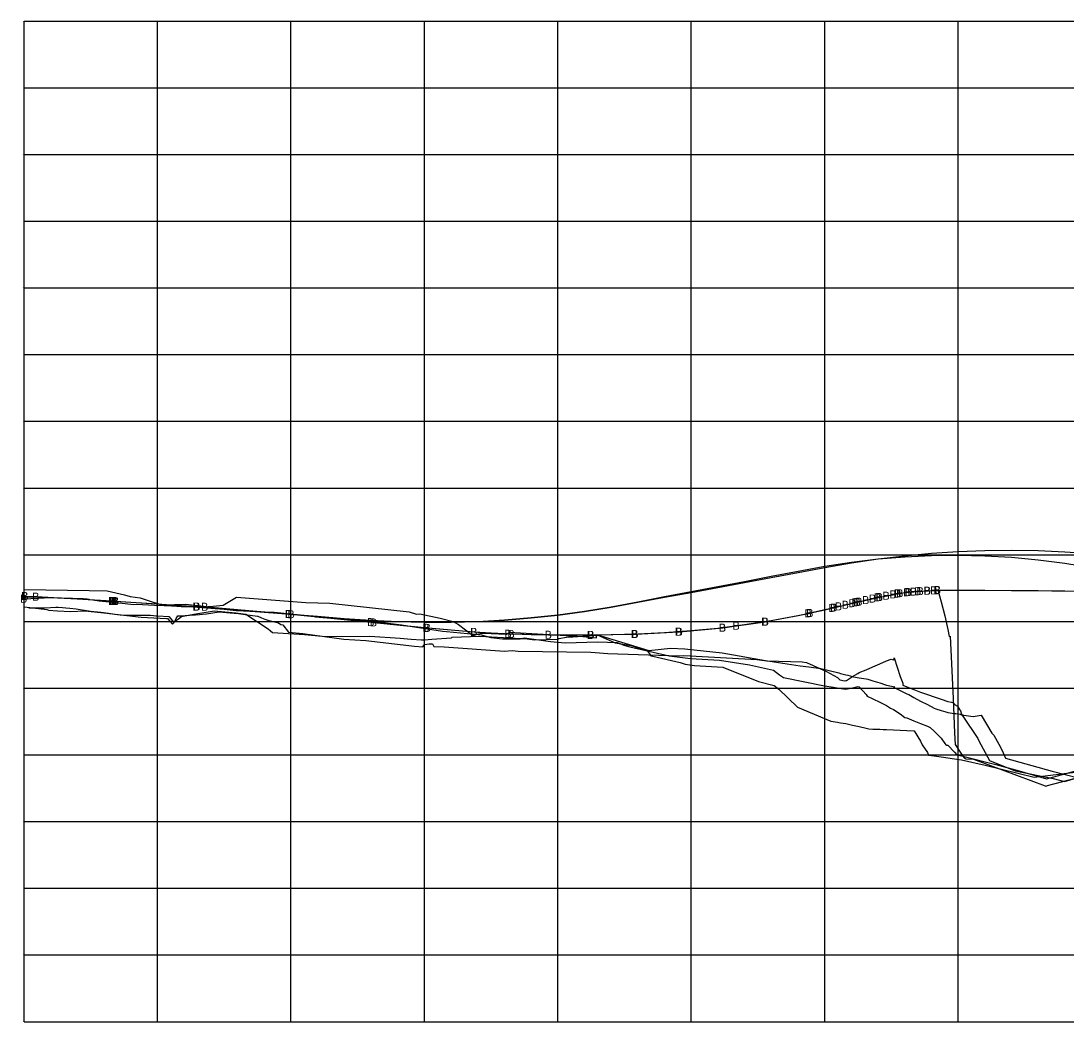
# Model space of a CAD drawing. Extents: x 76292 to 78417, y 50412 to 52585.
# Drawn here: x 76304.2 to 76695.8, y 50411.8 to 50787.4 of the extents above; entities that cross this region are included whole.
import ezdxf

# ---------------------------------------------------------------- set-up
doc = ezdxf.new("R2010")
doc.units = 0
for name, color, linetype in [('1', 7, 'Continuous'), ('2', 7, 'Continuous'), ('38', 7, 'Continuous'), ('5', 7, 'Continuous'), ('63', 7, 'Continuous')]:
    doc.layers.add(name, color=color, linetype=linetype)

msp = doc.modelspace()

# ---------------------------------------------------------------- linework, layer by layer
at = {"layer": '1'}
for p, q in [((76305.34, 50412.34), (78205.34, 50412.34)), ((76305.34, 50412.34), (76305.34, 50412.34)), ((76355.34, 50412.34), (76355.34, 50412.34)), ((76405.34, 50412.34), (76405.34, 50412.34)), ((76455.34, 50412.34), (76455.34, 50412.34)), ((76505.34, 50412.34), (76505.34, 50412.34)), ((76555.34, 50412.34), (76555.34, 50412.34)), ((76605.34, 50412.34), (76605.34, 50412.34)), ((76655.34, 50412.34), (76655.34, 50412.34))]:
    msp.add_line(p, q, dxfattribs=at)
for points in [[(76305.34, 50574.3), (76329.72, 50573.94), (76336.54, 50573.87), (76342.97, 50572.34), (76345.12, 50571.75), (76348.82, 50571.14), (76351.86, 50570.18), (76356.85, 50568.54), (76357.53, 50568.62), (76365.83, 50568.81), (76372.74, 50568.03), (76373.97, 50567.86), (76374.28, 50567.9), (76376.18, 50568.07), (76379.92, 50568.38), (76384.91, 50571.48), (76410.89, 50569.47), (76419.91, 50569.23), (76449.64, 50566), (76452.37, 50565.05), (76453.69, 50565.21), (76461.28, 50563.57), (76466.12, 50562.33), (76468.11, 50561.15), (76473.42, 50557.15), (76476.75, 50557.92), (76476.95, 50557.94), (76477.55, 50558), (76486.06, 50557.61), (76487.36, 50558.27), (76489.3, 50558.23), (76514.73, 50556.72), (76519.84, 50556.23), (76519.89, 50556.66), (76520.07, 50557.36), (76526.79, 50554.3), (76532.67, 50553.29), (76538.88, 50551.39), (76540.2, 50549.47), (76540.92, 50549.32), (76551.13, 50546.98), (76553.01, 50546.28), (76556.53, 50545.81), (76567.14, 50545.26), (76580.58, 50539.89), (76586.39, 50538.33), (76588.21, 50537.01), (76595.11, 50530.17), (76607.69, 50524.96), (76610.19, 50524.54), (76610.66, 50524.47), (76611.28, 50524.37), (76613.21, 50524.04), (76615.76, 50523.5), (76618.31, 50522.95), (76620.86, 50522.39), (76621.87, 50522.04), (76623.41, 50522.01), (76625.97, 50521.92), (76627.2, 50521.87), (76628.52, 50521.83), (76631.07, 50521.71), (76633.62, 50521.59), (76636.17, 50521.47), (76638.72, 50521.35), (76638.9, 50521.34), (76641.27, 50517.5), (76641.82, 50516.11), (76643.82, 50513.23), (76644.22, 50512.24), (76646.37, 50511.96), (76648.93, 50511.58), (76651.48, 50511.2), (76654.03, 50510.83), (76656.58, 50510.44), (76665.41, 50508.46), (76683.8, 50504.01), (76700.19, 50506.03)], [(76305.34, 50571.97), (76306.2, 50571.59), (76306.58, 50571.58), (76306.91, 50571.57), (76307.23, 50571.55), (76327.44, 50570.88), (76327.97, 50570.85), (76328.21, 50570.83), (76328.44, 50570.82), (76328.67, 50570.79), (76328.89, 50570.77), (76329.11, 50570.74), (76329.33, 50570.71), (76329.57, 50570.67), (76329.82, 50570.62), (76329.86, 50570.61), (76329.9, 50570.6), (76331.09, 50570.39), (76333.55, 50570.08), (76342.1, 50569.17), (76345.39, 50568.83), (76349.71, 50568.63), (76354.25, 50568.43), (76357.89, 50568.26), (76360.59, 50568.14), (76362.63, 50568.05), (76364.16, 50567.98), (76365.32, 50567.93), (76366.19, 50567.9), (76366.83, 50567.88), (76369.95, 50567.94), (76372.79, 50567.62), (76373.42, 50567.56), (76374.35, 50567.48), (76375.76, 50567.35), (76377.58, 50567.18), (76380.33, 50566.91), (76384.81, 50566.44), (76385.18, 50566.4), (76397.24, 50565.85), (76398.15, 50565.81), (76398.35, 50565.8), (76398.49, 50565.79), (76398.6, 50565.79), (76398.69, 50565.79), (76398.76, 50565.79), (76398.83, 50565.8), (76398.84, 50565.8), (76398.85, 50565.8), (76398.94, 50565.81), (76399.03, 50565.81), (76399.12, 50565.81), (76413.77, 50564.33), (76413.95, 50564.32), (76414.52, 50564.08), (76417.31, 50563.84), (76436.78, 50562.3), (76446.75, 50561.06), (76462.16, 50558.66), (76463.6, 50558.58), (76476.69, 50557.29), (76477.49, 50557.11), (76480.24, 50556.32), (76484.67, 50555.83), (76491.27, 50555.84), (76491.46, 50555.96), (76492.91, 50556.24), (76502.55, 50554.77), (76508.12, 50554.35), (76520.31, 50554.65), (76527.55, 50554.45), (76530.41, 50553.32), (76532.31, 50552.86), (76547.08, 50549.49), (76555.06, 50548.5), (76565.96, 50547.79), (76577.22, 50546.13), (76586.18, 50544.08), (76588.45, 50542.38), (76589.96, 50541.39), (76605.32, 50538.21), (76608.58, 50537.66), (76610.66, 50537.33), (76613.21, 50536.97), (76613.3, 50536.96), (76615.76, 50537.52), (76617.74, 50538), (76618.31, 50537.81), (76620.86, 50534.94), (76621.28, 50534.37), (76623.41, 50533.34), (76625.97, 50532.06), (76628.52, 50530.78), (76629.98, 50529.89), (76631.07, 50529.37), (76633.62, 50527.71), (76635.34, 50526.36), (76636.17, 50526.17), (76638.72, 50525.15), (76641.27, 50524.12), (76643.82, 50523.1), (76644.87, 50522.59), (76646.37, 50521.23), (76648.93, 50518.54), (76650.41, 50516.66), (76650.76, 50516.16), (76651.01, 50515.99), (76651.48, 50515.94), (76654.03, 50513.32), (76654.83, 50512.33), (76656.58, 50512), (76669.47, 50508.75), (76678.2, 50506.3), (76688.47, 50503.33), (76708.61, 50508.87)], [(76305.34, 50567.76), (76313.87, 50566.77), (76314.52, 50566.55), (76317.91, 50566.33), (76322.78, 50566.06), (76328.07, 50566.36), (76335.22, 50565.54), (76349.2, 50563.89), (76358.7, 50563.47), (76359.13, 50563.5), (76360.89, 50561.5), (76360.99, 50561.38), (76361.36, 50561.7), (76361.46, 50561.84), (76361.67, 50562.17), (76362.38, 50563.43), (76362.92, 50564.47), (76363.96, 50564.5), (76367.33, 50564.65), (76369.54, 50564.78), (76371.08, 50564.9), (76372.19, 50565.01), (76373.67, 50565.19), (76378.48, 50565.98), (76382.54, 50565.62), (76384.09, 50565.48), (76385.7, 50565.26), (76388.2, 50564.9), (76390.12, 50564.65), (76392.87, 50564.32), (76392.93, 50564.32), (76394.34, 50563.67), (76395.58, 50563.2), (76396.65, 50562.87), (76400.73, 50561.83), (76401.5, 50561.21), (76402.3, 50561.06), (76404.41, 50558.34), (76409.81, 50557.81), (76425.22, 50555.73), (76433.44, 50555.15), (76451.63, 50553.1), (76454.73, 50552.85), (76455.45, 50553.68), (76457.13, 50553.94), (76458.42, 50553.91), (76458.83, 50553.01), (76462.8, 50552.84), (76485.41, 50551.21), (76488.23, 50551.43), (76490.43, 50551.19), (76517.68, 50550.77), (76519.35, 50550.76), (76524.11, 50550.34), (76550.67, 50549.51), (76552.44, 50549.55), (76554.98, 50549.41), (76579.96, 50548.07), (76583.63, 50547.6), (76596.94, 50547.19), (76598.5, 50546.95), (76606.05, 50543.63), (76610.17, 50541.3), (76610.66, 50540.82), (76610.99, 50540.49), (76612.7, 50540.13), (76613.21, 50540.19), (76613.53, 50540.21), (76615.76, 50541.69), (76617.81, 50542.83), (76618.31, 50543.15), (76620.86, 50544.22), (76623.41, 50545.31), (76625.97, 50546.41), (76628.52, 50547.54), (76630.2, 50548.18), (76631.07, 50547.92), (76631.29, 50547.88), (76631.4, 50548.71), (76633.62, 50541.73), (76634.62, 50539.16), (76634.67, 50538.51), (76636.17, 50537.83), (76638.72, 50536.81), (76641.27, 50535.84), (76643.82, 50534.92), (76646.37, 50534.03), (76648.93, 50533.19), (76651.48, 50532.39), (76652.91, 50532.03), (76653.46, 50531.81), (76654.03, 50531.22), (76655.04, 50530.64), (76655.49, 50529.96), (76655.81, 50529.4), (76656.17, 50528.8), (76656.58, 50527.54), (76657.06, 50526.81), (76662.78, 50518.42), (76663.07, 50517.59), (76667.07, 50510.23), (76676.66, 50506.39), (76691, 50503.47), (76695.17, 50502.34), (76717.36, 50508.88)], [(76307.14, 50567.5), (76313.25, 50567.45), (76317.22, 50567.75), (76318.12, 50567.7), (76319.8, 50567.57), (76320.95, 50567.48), (76322.54, 50567.29), (76324.92, 50567.01), (76330.3, 50566.25), (76334.07, 50565.77), (76337, 50565.39), (76339.36, 50565.1), (76341.32, 50564.87), (76343, 50564.67), (76352.75, 50564.64), (76353.83, 50564.55), (76354.75, 50564.47), (76355.53, 50564.41), (76359.55, 50564.22), (76360.91, 50562.58), (76361.32, 50562.11), (76363.28, 50563.35), (76364.4, 50564.24), (76367.57, 50564.78), (76369.01, 50565.06), (76376.54, 50566.3), (76384.69, 50565.58), (76388.41, 50565.07), (76388.43, 50565.07), (76388.45, 50565.06), (76396.82, 50559.51), (76397.68, 50558.84), (76398.5, 50558.14), (76410.39, 50557.46), (76418.27, 50556.64), (76434.85, 50556.79), (76446.23, 50556.13), (76450.39, 50555.76), (76454.32, 50555.4), (76455.33, 50555.43), (76458.19, 50555.75), (76465.5, 50556.26), (76465.73, 50556.39), (76476.11, 50556.77), (76493.81, 50555.81), (76493.9, 50555.79), (76496.63, 50555.5), (76505.35, 50555.72), (76505.68, 50555.89), (76508.55, 50556.41), (76509.32, 50556.54), (76510.92, 50556.56), (76518.32, 50557.06), (76520.23, 50557.14), (76520.86, 50557.08), (76521.42, 50556.89), (76539.45, 50551.47), (76547.61, 50552.37), (76552.97, 50552.11), (76566.9, 50550.6), (76583.21, 50547.69), (76596.17, 50545.76), (76599.39, 50545.28), (76603.86, 50544.74), (76610.66, 50543.03), (76611.32, 50542.86), (76613.21, 50542.38), (76613.99, 50542.24), (76615.76, 50541.71), (76616.17, 50541.63), (76618.31, 50541.24), (76620.86, 50540.81), (76621.45, 50540.74), (76623.41, 50540.07), (76625.97, 50539.28), (76628.52, 50538.5), (76631.63, 50537.81), (76631.07, 50537.7), (76633.62, 50536.43), (76636.17, 50535.17), (76636.89, 50534.91), (76638.72, 50533.85), (76641.27, 50532.52), (76643.82, 50531.2), (76646.37, 50529.9), (76647.04, 50529.65), (76648.93, 50528.95), (76650.75, 50528.48), (76651.48, 50528.27), (76654.03, 50527.84), (76654.43, 50527.78), (76656.17, 50527.6), (76656.58, 50527.4), (76660.96, 50526.69), (76664, 50527.25), (76668.02, 50520.51), (76668.66, 50519.7), (76670.53, 50516.34), (76671.86, 50513.98), (76673.1, 50511.07), (76690.6, 50506.27), (76700.36, 50503.69)]]:
    msp.add_lwpolyline(points, dxfattribs=at)
at = {"layer": '2'}
msp.add_lwpolyline([(76305.34, 50570.82), (76305.72, 50571.85), (76305.74, 50571.85), (76305.77, 50571.85), (76305.8, 50571.85), (76305.83, 50571.85), (76305.84, 50571.85), (76309.89, 50571.63), (76338.41, 50570.03), (76338.7, 50570.02), (76339, 50570), (76339.5, 50569.97), (76339.8, 50569.96), (76369.99, 50567.91), (76370.25, 50567.92), (76373.18, 50567.84), (76404.5, 50565.14), (76404.62, 50565.12), (76404.68, 50565.12), (76405.52, 50565.03), (76435.43, 50562.08), (76436.4, 50561.97), (76456.09, 50559.97), (76456.59, 50559.93), (76473.97, 50558.42), (76474.05, 50558.42), (76486.85, 50557.74), (76487.97, 50557.68), (76501.91, 50557.35), (76501.93, 50557.35), (76517.76, 50557.29), (76517.89, 50557.29), (76534.15, 50557.63), (76534.4, 50557.63), (76550.72, 50558.49), (76550.95, 50558.49), (76567.13, 50560), (76567.22, 50560), (76572.33, 50560.73), (76583.06, 50562.23), (76583.23, 50562.26), (76599.28, 50565.38), (76599.93, 50565.51), (76608.26, 50567.43), (76608.82, 50567.54), (76610.66, 50567.98), (76613.21, 50568.58), (76615.76, 50569.19), (76616.91, 50569.46), (76617.63, 50569.6), (76618.31, 50569.76), (76620.86, 50570.34), (76623.41, 50570.92), (76625.24, 50571.34), (76625.82, 50571.45), (76625.97, 50571.48), (76628.52, 50571.98), (76631.07, 50572.47), (76632.57, 50572.77), (76632.88, 50572.82), (76633.62, 50572.92), (76636.17, 50573.27), (76636.7, 50573.34), (76636.81, 50573.35), (76638.72, 50573.51), (76640.29, 50573.65), (76640.34, 50573.65), (76641.27, 50573.7), (76643.82, 50573.84), (76643.83, 50573.84), (76643.83, 50573.84), (76643.97, 50573.85), (76646.37, 50573.97), (76647.58, 50574.04), (76647.59, 50574.04), (76647.72, 50574.16), (76648.93, 50569.68), (76650.35, 50564.4), (76651.48, 50559.28), (76652.04, 50556.72), (76652.36, 50556.83), (76653.53, 50533.51), (76654.03, 50520.61), (76654.2, 50516.24), (76656.58, 50512.61), (76657.01, 50511.95), (76657.75, 50511.05), (76658.21, 50510.8), (76661.15, 50510.68), (76687.95, 50500.72), (76688.19, 50500.65), (76688.63, 50500.78), (76688.77, 50500.8), (76709.75, 50506.34)], dxfattribs=at)
at = {"layer": '38'}
for points in [[(76355.34, 50568.89), (76365.34, 50568.12), (76375.34, 50567.35), (76385.34, 50566.58), (76395.34, 50565.81), (76405.34, 50565.04), (76415.34, 50564.27), (76425.34, 50563.5), (76435.34, 50562.77), (76445.34, 50562.26), (76455.34, 50562.02), (76465.34, 50562.04), (76475.34, 50562.32), (76485.34, 50562.87), (76495.34, 50563.68), (76505.34, 50564.75), (76515.34, 50566.09), (76525.34, 50567.69), (76535.34, 50569.52), (76545.34, 50571.39), (76555.34, 50573.25), (76565.34, 50575.12), (76575.34, 50576.98), (76585.34, 50578.85), (76595.34, 50580.71), (76605.34, 50582.58), (76615.34, 50584.31), (76625.34, 50585.77), (76635.34, 50586.96), (76645.34, 50587.88), (76655.34, 50588.53), (76665.34, 50588.91), (76675.34, 50589.03), (76685.34, 50588.87), (76695.34, 50588.45), (76705.34, 50587.75)], [(76355.34, 50568.89), (76365.34, 50568.12), (76375.34, 50567.35), (76385.34, 50566.58), (76395.34, 50565.81), (76405.34, 50565.04), (76415.34, 50564.27), (76425.34, 50563.5), (76435.34, 50562.77), (76445.34, 50562.27), (76455.34, 50562.03), (76465.34, 50562.06), (76475.34, 50562.36), (76485.34, 50562.93), (76495.34, 50563.76), (76505.34, 50564.86), (76515.34, 50566.23), (76525.34, 50567.87), (76535.34, 50569.74), (76545.34, 50571.64), (76555.34, 50573.55), (76565.34, 50575.45), (76575.34, 50577.35), (76585.34, 50579.26), (76595.34, 50581.16), (76605.34, 50583.02), (76615.34, 50584.57), (76625.34, 50585.76), (76635.34, 50586.6), (76645.34, 50587.09), (76655.34, 50587.21), (76665.34, 50586.99), (76675.34, 50586.41), (76685.34, 50585.47), (76695.34, 50584.18), (76705.34, 50582.53)], [(76305.34, 50570.83), (76315.34, 50571.32), (76325.34, 50570.77), (76335.34, 50570.21), (76345.34, 50569.58), (76355.34, 50568.9), (76365.34, 50568.22), (76375.34, 50567.65), (76385.34, 50566.79), (76395.34, 50565.93), (76405.34, 50565.05), (76415.34, 50564.06), (76425.34, 50563.07), (76435.34, 50562.09), (76445.34, 50561.06), (76455.34, 50560.04), (76465.34, 50559.17), (76475.34, 50558.35), (76485.34, 50557.82), (76495.34, 50557.51), (76505.34, 50557.34), (76515.34, 50557.3), (76525.34, 50557.44), (76535.34, 50557.67), (76545.34, 50558.2), (76555.34, 50558.9), (76565.34, 50559.83), (76575.34, 50561.15), (76585.34, 50562.67), (76595.34, 50564.61), (76605.34, 50566.75), (76615.34, 50569.09), (76625.34, 50571.36), (76635.34, 50573.15), (76645.34, 50573.92), (76655.34, 50574.11), (76665.34, 50574.03), (76675.34, 50573.96), (76685.34, 50573.88), (76695.34, 50573.81), (76705.34, 50573.73)], [(76305.34, 50570.83), (76315.34, 50571.32), (76325.34, 50570.77), (76335.34, 50570.21), (76345.34, 50569.58), (76355.34, 50568.9), (76365.34, 50568.22), (76375.34, 50567.65), (76385.34, 50566.79), (76395.34, 50565.93), (76405.34, 50565.05), (76415.34, 50564.06), (76425.34, 50563.07), (76435.34, 50562.09), (76445.34, 50561.06), (76455.34, 50560.04), (76465.34, 50559.17), (76475.34, 50558.35), (76485.34, 50557.82), (76495.34, 50557.51), (76505.34, 50557.34), (76515.34, 50557.3), (76525.34, 50557.44), (76535.34, 50557.67), (76545.34, 50558.2), (76555.34, 50558.9), (76565.34, 50559.83), (76575.34, 50561.15), (76585.34, 50562.67), (76595.34, 50564.61), (76605.34, 50566.75), (76615.34, 50569.09), (76625.34, 50571.36), (76635.34, 50573.15), (76645.34, 50573.92), (76655.34, 50574.11), (76665.34, 50574.03), (76675.34, 50573.96), (76685.34, 50573.88), (76695.34, 50573.81), (76705.34, 50573.73)]]:
    msp.add_lwpolyline(points, dxfattribs=at)
at = {"layer": '5'}
for p, q in [((76305.34, 50570.82), (76305.72, 50571.85)), ((76305.72, 50571.85), (76305.74, 50571.85)), ((76305.74, 50571.85), (76305.77, 50571.85)), ((76305.77, 50571.85), (76305.8, 50571.85)), ((76305.8, 50571.85), (76305.83, 50571.85)), ((76305.83, 50571.85), (76305.84, 50571.85)), ((76305.84, 50571.85), (76309.89, 50571.63)), ((76309.89, 50571.63), (76338.41, 50570.03)), ((76618.31, 50569.76), (76620.86, 50570.34)), ((76620.86, 50570.34), (76623.41, 50570.92)), ((76623.41, 50570.92), (76625.24, 50571.34)), ((76625.24, 50571.34), (76625.82, 50571.45)), ((76625.82, 50571.45), (76625.97, 50571.48)), ((76625.97, 50571.48), (76628.52, 50571.98)), ((76628.52, 50571.98), (76631.07, 50572.47)), ((76631.07, 50572.47), (76632.57, 50572.77)), ((76632.57, 50572.77), (76632.88, 50572.82)), ((76632.88, 50572.82), (76633.62, 50572.92)), ((76633.62, 50572.92), (76636.17, 50573.27)), ((76636.17, 50573.27), (76636.7, 50573.34)), ((76636.7, 50573.34), (76636.81, 50573.35)), ((76636.81, 50573.35), (76638.72, 50573.51)), ((76638.72, 50573.51), (76640.29, 50573.65)), ((76640.29, 50573.65), (76640.34, 50573.65)), ((76640.34, 50573.65), (76641.27, 50573.7)), ((76641.27, 50573.7), (76643.82, 50573.84)), ((76643.82, 50573.84), (76643.83, 50573.84)), ((76643.83, 50573.84), (76643.97, 50573.85)), ((76643.83, 50573.84), (76643.83, 50573.84)), ((76643.97, 50573.85), (76646.37, 50573.97)), ((76646.37, 50573.97), (76647.58, 50574.04)), ((76647.58, 50574.04), (76647.59, 50574.04)), ((76647.59, 50574.04), (76647.72, 50574.16)), ((76647.72, 50574.16), (76725.17, 50573.59)), ((76338.41, 50570.03), (76338.7, 50570.02)), ((76338.7, 50570.02), (76339, 50570)), ((76339, 50570), (76339.5, 50569.97)), ((76339.5, 50569.97), (76339.8, 50569.96)), ((76339.8, 50569.96), (76369.99, 50567.91)), ((76369.99, 50567.91), (76370.25, 50567.92)), ((76370.25, 50567.92), (76373.18, 50567.84)), ((76373.18, 50567.84), (76404.5, 50565.14)), ((76599.93, 50565.51), (76608.26, 50567.43)), ((76608.26, 50567.43), (76608.82, 50567.54)), ((76608.82, 50567.54), (76610.66, 50567.98)), ((76610.66, 50567.98), (76613.21, 50568.58)), ((76613.21, 50568.58), (76615.76, 50569.19)), ((76615.76, 50569.19), (76616.91, 50569.46)), ((76616.91, 50569.46), (76617.63, 50569.6)), ((76617.63, 50569.6), (76618.31, 50569.76)), ((76404.5, 50565.14), (76404.62, 50565.12)), ((76404.62, 50565.12), (76404.68, 50565.12)), ((76404.68, 50565.12), (76405.52, 50565.03)), ((76405.52, 50565.03), (76435.43, 50562.08)), ((76583.23, 50562.26), (76599.28, 50565.38)), ((76599.28, 50565.38), (76599.93, 50565.51)), ((76435.43, 50562.08), (76436.4, 50561.97)), ((76436.4, 50561.97), (76456.09, 50559.97)), ((76456.09, 50559.97), (76456.59, 50559.93)), ((76456.59, 50559.93), (76473.97, 50558.42)), ((76550.95, 50558.49), (76567.13, 50560)), ((76567.13, 50560), (76567.22, 50560)), ((76567.22, 50560), (76572.33, 50560.73)), ((76572.33, 50560.73), (76583.06, 50562.23)), ((76583.06, 50562.23), (76583.23, 50562.26)), ((76473.97, 50558.42), (76474.05, 50558.42)), ((76474.05, 50558.42), (76486.85, 50557.74)), ((76486.85, 50557.74), (76487.97, 50557.68)), ((76487.97, 50557.68), (76501.91, 50557.35)), ((76501.91, 50557.35), (76501.93, 50557.35)), ((76501.93, 50557.35), (76517.76, 50557.29)), ((76517.76, 50557.29), (76517.89, 50557.29)), ((76517.89, 50557.29), (76534.15, 50557.63)), ((76534.15, 50557.63), (76534.4, 50557.63)), ((76534.4, 50557.63), (76550.72, 50558.49)), ((76550.72, 50558.49), (76550.95, 50558.49))]:
    msp.add_line(p, q, dxfattribs=at)
at = {"layer": '63'}
for p, q in [((76305.34, 50412.34), (76305.34, 50787.34)), ((76305.34, 50787.34), (76305.34, 50787.34)), ((76305.34, 50787.34), (76305.34, 50787.34)), ((76305.34, 50787.34), (78205.34, 50787.34)), ((76305.34, 50787.34), (78205.34, 50787.34)), ((76355.34, 50412.34), (76355.34, 50787.34)), ((76405.34, 50412.34), (76405.34, 50787.34)), ((76455.34, 50412.34), (76455.34, 50787.34)), ((76505.34, 50412.34), (76505.34, 50787.34)), ((76555.34, 50412.34), (76555.34, 50787.34)), ((76605.34, 50412.34), (76605.34, 50787.34)), ((76655.34, 50412.34), (76655.34, 50787.34)), ((76305.34, 50762.34), (76305.34, 50762.34)), ((76305.34, 50762.34), (78205.34, 50762.34)), ((76305.34, 50737.34), (76305.34, 50737.34)), ((76305.34, 50737.34), (78205.34, 50737.34)), ((76305.34, 50712.34), (76305.34, 50712.34)), ((76305.34, 50712.34), (78205.34, 50712.34)), ((76305.34, 50687.34), (76305.34, 50687.34)), ((76305.34, 50687.34), (78205.34, 50687.34)), ((76305.34, 50662.34), (76305.34, 50662.34)), ((76305.34, 50662.34), (78205.34, 50662.34)), ((76305.34, 50637.34), (76305.34, 50637.34)), ((76305.34, 50637.34), (78205.34, 50637.34)), ((76305.34, 50612.34), (76305.34, 50612.34)), ((76305.34, 50612.34), (78205.34, 50612.34)), ((76305.34, 50587.34), (76305.34, 50587.34)), ((76305.34, 50587.34), (78205.34, 50587.34)), ((76305.34, 50562.34), (76305.34, 50562.34)), ((76305.34, 50562.34), (78205.34, 50562.34)), ((76305.34, 50537.34), (76305.34, 50537.34)), ((76305.34, 50537.34), (78205.34, 50537.34)), ((76305.34, 50512.34), (76305.34, 50512.34)), ((76305.34, 50512.34), (78205.34, 50512.34)), ((76305.34, 50487.34), (76305.34, 50487.34)), ((76305.34, 50487.34), (78205.34, 50487.34)), ((76305.34, 50462.34), (76305.34, 50462.34)), ((76305.34, 50462.34), (78205.34, 50462.34)), ((76305.34, 50437.34), (76305.34, 50437.34)), ((76305.34, 50437.34), (78205.34, 50437.34)), ((76305.34, 50412.34), (76305.34, 50412.34))]:
    msp.add_line(p, q, dxfattribs=at)

# ---------------------------------------------------------------- texts
at = {"layer": '1'}
for s, p in [('80', (76305.4, 50411.93)), ('+50', (76355.4, 50411.81)), ('81', (76405.4, 50411.96)), ('+50', (76455.4, 50411.81)), ('82', (76505.4, 50411.94)), ('+50', (76555.4, 50411.81)), ('83', (76605.4, 50411.94)), ('+50', (76655.4, 50411.81))]:
    msp.add_text(s, height=0.12, rotation=90, dxfattribs=at).set_placement(p)
at = {"layer": '5'}
for p in [(76631.07, 50571.27), (76631.38, 50571.32), (76632.12, 50571.42), (76634.67, 50571.77), (76635.2, 50571.84), (76635.31, 50571.85), (76637.22, 50572.01), (76638.79, 50572.15), (76638.84, 50572.15), (76639.77, 50572.2), (76642.32, 50572.34), (76642.33, 50572.34), (76642.33, 50572.34), (76642.47, 50572.35), (76644.87, 50572.47), (76646.08, 50572.54), (76646.09, 50572.54), (76646.22, 50572.66), (76303.84, 50569.32), (76304.22, 50570.35), (76304.24, 50570.35), (76304.27, 50570.35), (76304.3, 50570.35), (76304.33, 50570.35), (76304.34, 50570.35), (76308.39, 50570.13), (76336.91, 50568.53), (76337.2, 50568.52), (76337.5, 50568.5), (76338, 50568.47), (76338.3, 50568.46), (76614.26, 50567.69), (76615.41, 50567.96), (76616.13, 50568.1), (76616.81, 50568.26), (76619.36, 50568.84), (76621.91, 50569.42), (76623.74, 50569.84), (76624.32, 50569.95), (76624.47, 50569.98), (76627.02, 50570.48), (76629.57, 50570.97), (76368.49, 50566.41), (76368.75, 50566.42), (76371.68, 50566.34), (76403, 50563.64), (76403.12, 50563.62), (76403.18, 50563.62), (76404.02, 50563.53), (76597.78, 50563.88), (76598.43, 50564.01), (76606.76, 50565.93), (76607.32, 50566.04), (76609.16, 50566.48), (76611.71, 50567.08), (76433.93, 50560.58), (76434.9, 50560.47), (76581.56, 50560.73), (76581.73, 50560.76), (76454.59, 50558.47), (76455.09, 50558.43), (76472.47, 50556.92), (76472.55, 50556.92), (76485.35, 50556.24), (76486.47, 50556.18), (76500.41, 50555.85), (76500.43, 50555.85), (76516.26, 50555.79), (76516.39, 50555.79), (76532.65, 50556.13), (76532.9, 50556.13), (76549.22, 50556.99), (76549.45, 50556.99), (76565.63, 50558.5), (76565.72, 50558.5), (76570.83, 50559.23)]:
    msp.add_text('B', height=3, dxfattribs=at).set_placement(p)
at = {"layer": '63'}
for s, height, p in [('945', 0.12, (76304.81, 50787.28)), ('945', 0.12, (76304.81, 50787.28)), ('940', 0.12, (76304.8, 50762.28)), ('935', 0.12, (76304.81, 50737.28)), ('930', 0.12, (76304.8, 50712.28)), ('925', 0.12, (76304.81, 50687.28)), ('920', 0.12, (76304.8, 50662.28)), ('915', 0.12, (76304.81, 50637.28)), ('910', 0.12, (76304.8, 50612.28)), ('905', 0.12, (76304.81, 50587.28)), ('900', 0.12, (76304.8, 50562.28)), ('895', 0.12, (76304.81, 50537.28)), ('890', 0.12, (76304.8, 50512.28)), ('885', 0.12, (76304.81, 50487.28)), ('880', 0.12, (76304.8, 50462.28)), ('875', 0.12, (76304.81, 50437.28)), ('870', 0.12, (76304.8, 50412.28)), ('-', 0.0001, (76305.34, 50412.34))]:
    msp.add_text(s, height=height, dxfattribs=at).set_placement(p)

doc.saveas('drawing.dxf')
